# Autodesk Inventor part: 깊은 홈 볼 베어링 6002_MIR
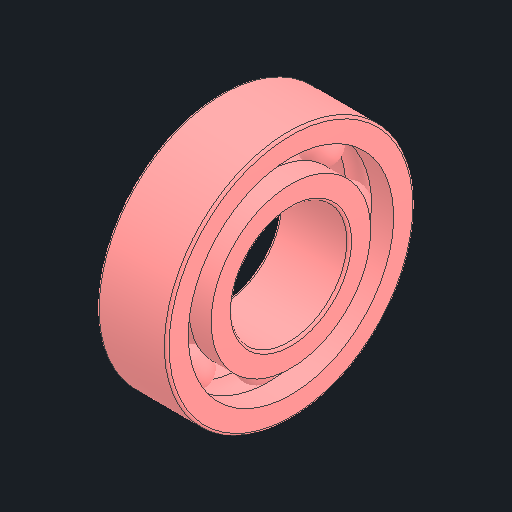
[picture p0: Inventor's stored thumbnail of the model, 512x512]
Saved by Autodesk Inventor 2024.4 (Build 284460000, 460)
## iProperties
Created: 2025-10
Part Number: 깊은 홈 볼 베어링 6002_MIR
Material: 강철, 연강
Description: 깊은 그루브 볼 베어링
Document SubType Name: Modeling
Designer: user
Density: 7.85 g/cm^3
Appearance: 기본값
Author: jhkim
Sending System: Autodesk Inventor 2026
Preprocessor: ST-DEVELOPER v20.1
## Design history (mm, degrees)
derived "깊은 홈 볼 베어링 6002.ipt"
feature "솔리드1::깊은 홈 볼 베어링 6002.ipt"
feature "솔리드2::깊은 홈 볼 베어링 6002.ipt"
feature "솔리드3::깊은 홈 볼 베어링 6002.ipt"
feature "솔리드4::깊은 홈 볼 베어링 6002.ipt"
feature "솔리드5::깊은 홈 볼 베어링 6002.ipt"
feature "솔리드6::깊은 홈 볼 베어링 6002.ipt"
feature "솔리드7::깊은 홈 볼 베어링 6002.ipt"
feature "솔리드8::깊은 홈 볼 베어링 6002.ipt"
feature "솔리드9::깊은 홈 볼 베어링 6002.ipt"
feature "솔리드10::깊은 홈 볼 베어링 6002.ipt"
tag "피쳐 태그1"
node "솔리드1"
node "솔리드2"
node "솔리드3"
node "솔리드4"
node "솔리드5"
node "솔리드6"
node "솔리드7"
node "솔리드8"
node "솔리드9"
node "솔리드10"
